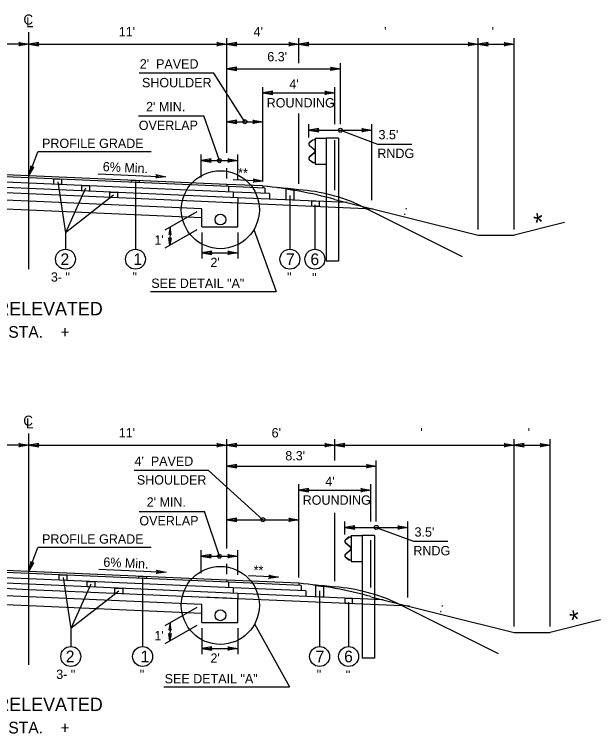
# Model space of a CAD drawing. Extents: x -592 to 1199, y -590 to 416.
# Drawn here: x 814.3 to 902, y 160.9 to 268.6 of the extents above; entities that cross this region are included whole.
import ezdxf

# ---------------------------------------------------------------- set-up
doc = ezdxf.new("R2010")
doc.units = 0
doc.layers.add('1', color=7, linetype='Continuous')
doc.layers.add('Des_ Drain_ Ftrs', color=7, linetype='Continuous')

msp = doc.modelspace()

# ---------------------------------------------------------------- linework, layer by layer
at = {"layer": '1'}
for p, q in [((816.45, 230.46), (816.45, 265.91)), ((846.08, 247.85), (846.08, 265.03)), ((856.86, 261.3), (856.86, 265.03)), ((883.68, 236.42), (883.68, 265.03)), ((889.06, 236.42), (889.06, 265.03)), ((816.45, 264.15), (786.81, 264.15)), ((816.45, 264.15), (846.08, 264.15)), ((846.08, 264.15), (856.86, 264.15)), ((856.86, 264.15), (883.68, 264.15)), ((883.68, 264.15), (889.06, 264.15)), ((863.06, 252.14), (863.06, 261.3)), ((844.12, 259.78), (832.98, 259.78)), ((848.78, 252.52), (844.13, 259.78)), ((846.08, 260.42), (863.06, 260.42)), ((851.47, 243.79), (851.47, 257.72)), ((862.25, 252.14), (862.25, 257.72)), ((851.47, 256.84), (862.25, 256.84)), ((832.88, 253.39), (842.65, 253.39)), ((844.98, 246.72), (842.65, 253.39)), ((856.86, 243.23), (856.86, 253.74)), ((846.08, 252.52), (851.47, 252.52)), ((858.36, 250.19), (858.36, 252.14)), ((867.75, 240.78), (867.75, 252.14)), ((858.36, 251.26), (867.75, 251.26)), ((863.06, 251.26), (868.61, 249.19)), ((858.96, 249.79), (858.45, 249.4)), ((858.97, 249.77), (858.46, 249.38)), ((859.28, 249.85), (858.96, 249.79)), ((859.28, 249.82), (858.97, 249.77)), ((859.28, 250.08), (859.28, 246.15)), ((859.28, 250.08), (860.96, 250.08)), ((860.96, 250.08), (860.96, 231.68)), ((862.79, 250.08), (860.96, 250.08)), ((862.25, 242.26), (862.25, 249.76)), ((862.79, 250.08), (862.79, 231.68)), ((858.43, 248.97), (859.16, 248.34)), ((858.45, 248.99), (859.18, 248.36)), ((868.61, 249.19), (873.77, 249.19)), ((816.45, 244.44), (817.83, 248.01)), ((834.74, 248.01), (817.83, 248.01)), ((842.24, 244.19), (842.24, 247.6)), ((847.73, 243.95), (847.73, 247.6)), ((859.16, 247.89), (858.43, 247.25)), ((859.18, 247.86), (858.45, 247.23)), ((859.25, 248.15), (859.25, 248.07)), ((859.28, 248.15), (859.28, 248.07)), ((842.24, 246.72), (847.73, 246.72)), ((858.45, 246.82), (858.96, 246.43)), ((858.46, 246.84), (858.97, 246.46)), ((816.45, 244.14), (786.47, 245.45)), ((816.45, 244.44), (786.81, 245.73)), ((846.08, 244.02), (846.08, 245.59)), ((858.96, 246.43), (859.28, 246.37)), ((858.97, 246.46), (859.28, 246.4)), ((859.28, 246.15), (860.96, 246.15)), ((816.45, 243.33), (785.55, 244.68)), ((846.09, 243.14), (816.45, 244.44)), ((826.84, 244.74), (836.95, 244.29)), ((816.45, 242.52), (784.62, 243.91)), ((846.32, 242.83), (816.45, 244.14)), ((847.03, 241.99), (816.45, 243.33)), ((820.78, 243.54), (821.94, 235.92)), ((832.41, 243.58), (832.41, 233.43)), ((851.53, 243.65), (847.04, 243.85)), ((816.45, 241.71), (784.64, 243.1)), ((847.73, 241.15), (816.45, 242.52)), ((824.95, 242.56), (821.94, 235.92)), ((851.47, 242.91), (846.09, 243.14)), ((846.09, 243.14), (846.09, 242.84)), ((851.77, 242.6), (846.32, 242.83)), ((846.32, 242.83), (846.32, 242.02)), ((851.47, 242.91), (851.47, 242.61)), ((851.77, 242.6), (851.77, 241.79)), ((816.45, 240.63), (790.01, 241.79)), ((842.25, 240.58), (816.45, 241.71)), ((829.13, 241.55), (821.94, 235.92)), ((852.46, 241.76), (847.03, 241.99)), ((847.03, 241.99), (847.03, 241.18)), ((847.73, 241.15), (847.73, 240.35)), ((864.08, 240.44), (847.73, 241.15)), ((852.46, 241.76), (852.46, 240.95)), ((855.51, 241.48), (855.51, 233.43)), ((858.36, 242.13), (858.36, 242.13)), ((816.45, 239.28), (790.01, 240.44)), ((842.34, 239.5), (816.45, 240.63)), ((847.73, 240.34), (842.25, 240.58)), ((847.74, 240.34), (846.09, 240.42)), ((867.99, 239.46), (847.73, 240.35)), ((847.73, 236.81), (847.73, 240.34)), ((859.25, 240.09), (859.25, 233.43)), ((862.25, 240.9), (883.68, 235.54)), ((842.34, 238.15), (816.45, 239.28)), ((841.58, 239.06), (836.82, 236.31)), ((842.34, 236.81), (842.34, 239.5)), ((842.34, 239.5), (842.34, 239.5)), ((866.25, 239.9), (881.3, 232.37)), ((896.6, 237.42), (889.06, 235.54)), ((821.94, 235.92), (821.94, 233.43)), ((841.58, 236.37), (836.81, 233.61)), ((837.59, 236.75), (837.57, 234.05)), ((842.34, 236.81), (847.73, 236.81)), ((842.34, 235.93), (842.34, 232.04)), ((847.73, 235.93), (847.73, 232.04)), ((850.14, 236.41), (853.47, 227.14)), ((883.68, 235.54), (889.06, 235.54)), ((842.34, 232.92), (847.73, 232.92)), ((862.79, 231.68), (860.96, 231.68)), ((834.68, 227.14), (853.47, 227.14)), ((816.45, 171.24), (816.45, 205.88)), ((846.08, 188.63), (846.08, 205)), ((862.25, 201.84), (862.25, 205)), ((889.07, 176.96), (889.07, 205)), ((894.46, 176.96), (894.46, 205)), ((816.45, 204.12), (786.81, 204.12)), ((816.45, 204.12), (846.08, 204.12)), ((846.08, 204.12), (862.25, 204.12)), ((862.25, 204.12), (889.07, 204.12)), ((889.07, 204.12), (894.46, 204.12)), ((868.44, 192.69), (868.44, 201.84)), ((843.36, 200.32), (832.21, 200.32)), ((851.47, 192.96), (843.36, 200.32)), ((846.08, 200.96), (868.44, 200.96)), ((856.86, 184.33), (856.86, 198.27)), ((867.64, 192.69), (867.64, 198.27)), ((856.86, 197.39), (867.64, 197.39)), ((832.97, 194.21), (842.73, 194.21)), ((844.98, 187.5), (842.73, 194.21)), ((862.25, 183.78), (862.25, 193.99)), ((846.08, 192.96), (856.86, 192.96)), ((863.75, 190.73), (863.75, 192.69)), ((873.14, 181.34), (873.14, 192.69)), ((863.75, 191.81), (873.14, 191.81)), ((868.44, 191.81), (874, 189.73)), ((864.67, 190.62), (864.67, 186.69)), ((864.67, 190.62), (866.35, 190.62)), ((866.35, 190.62), (866.35, 172.22)), ((868.18, 190.62), (866.35, 190.62)), ((868.18, 190.62), (868.18, 172.22)), ((863.82, 189.52), (864.55, 188.88)), ((864.35, 190.34), (863.83, 189.95)), ((863.84, 189.54), (864.57, 188.9)), ((864.36, 190.31), (863.85, 189.92)), ((864.67, 190.39), (864.35, 190.34)), ((864.67, 190.36), (864.36, 190.31)), ((867.64, 182.81), (867.64, 189.88)), ((874, 189.73), (879.16, 189.73)), ((816.45, 185.22), (817.83, 188.79)), ((834.74, 188.79), (817.83, 188.79)), ((842.24, 184.97), (842.24, 188.38)), ((847.73, 184.73), (847.73, 188.38)), ((864.55, 188.43), (863.82, 187.79)), ((864.57, 188.41), (863.84, 187.77)), ((864.64, 188.69), (864.64, 188.62)), ((864.67, 188.69), (864.67, 188.62)), ((842.24, 187.5), (847.73, 187.5)), ((863.83, 187.36), (864.35, 186.97)), ((863.85, 187.39), (864.36, 187)), ((816.45, 184.92), (786.47, 186.23)), ((816.45, 185.22), (786.81, 186.51)), ((846.08, 184.8), (846.08, 186.37)), ((864.35, 186.97), (864.67, 186.92)), ((864.36, 187), (864.67, 186.95)), ((864.67, 186.69), (866.35, 186.69)), ((816.45, 184.11), (785.55, 185.46)), ((846.09, 183.92), (816.45, 185.22)), ((826.91, 185.54), (837.02, 185.1)), ((816.45, 183.3), (784.62, 184.69)), ((846.32, 183.61), (816.45, 184.92)), ((847.03, 182.77), (816.45, 184.11)), ((821.58, 184.29), (822.74, 176.66)), ((833.48, 184.3), (833.48, 173.98)), ((853.83, 184.34), (849.34, 184.54)), ((816.45, 182.49), (784.62, 183.88)), ((847.73, 181.93), (816.45, 183.3)), ((825.75, 183.3), (822.74, 176.66)), ((856.86, 183.45), (846.09, 183.92)), ((846.09, 183.92), (846.09, 183.62)), ((846.32, 183.61), (846.32, 182.8)), ((857.19, 183.14), (846.33, 183.61)), ((856.86, 183.45), (856.86, 183.15)), ((857.19, 183.14), (857.19, 182.33)), ((816.45, 181.41), (790.01, 182.57)), ((847.73, 181.12), (816.45, 182.49)), ((829.93, 182.29), (822.74, 176.66)), ((847.03, 182.77), (847.03, 181.96)), ((857.89, 182.3), (847.04, 182.77)), ((847.73, 181.93), (847.73, 181.12)), ((869.48, 180.98), (847.75, 181.93)), ((857.89, 182.3), (857.89, 181.49)), ((859.96, 182.32), (859.96, 173.98)), ((863.75, 182.67), (863.75, 182.67)), ((816.45, 180.06), (790.01, 181.22)), ((842.34, 180.28), (816.45, 181.41)), ((846.08, 181.2), (842.25, 181.36)), ((847.73, 181.12), (846.07, 181.2)), ((847.73, 177.59), (847.73, 181.12)), ((873.39, 180), (847.73, 181.12)), ((867.64, 181.44), (889.07, 176.08)), ((842.34, 178.93), (816.45, 180.06)), ((841.58, 179.84), (836.82, 177.09)), ((842.34, 177.59), (842.34, 180.28)), ((842.34, 180.28), (842.34, 180.28)), ((864.3, 180.63), (864.3, 173.98)), ((871.64, 180.44), (886.69, 172.92)), ((902, 177.97), (894.46, 176.08)), ((822.74, 176.66), (822.74, 173.98)), ((841.58, 177.15), (836.81, 174.39)), ((837.59, 177.53), (837.57, 174.83)), ((842.34, 177.59), (847.73, 177.59)), ((842.34, 176.71), (842.34, 172.82)), ((847.73, 176.71), (847.73, 172.82)), ((850.24, 177.36), (855.46, 167.97)), ((889.07, 176.08), (894.46, 176.08)), ((842.34, 173.7), (847.73, 173.7)), ((868.18, 172.22), (866.35, 172.22)), ((836.68, 167.97), (855.46, 167.97))]:
    msp.add_line(p, q, dxfattribs=at)
for points in [[(820.21, 243.97), (821.35, 243.92), (821.35, 243.11), (820.21, 243.16)], [(831.83, 243.77), (832.98, 243.71), (832.98, 243.42), (831.83, 243.47)], [(824.38, 242.98), (825.53, 242.93), (825.53, 242.12), (824.38, 242.17)], [(854.94, 242.46), (856.08, 242.27), (856.08, 240.79), (854.94, 240.84)], [(828.56, 241.99), (829.7, 241.94), (829.7, 241.13), (828.56, 241.18)], [(858.79, 240.68), (859.9, 240.63), (859.9, 239.82), (858.79, 239.87)], [(821, 184.72), (822.15, 184.67), (822.15, 183.86), (821, 183.91)], [(832.91, 184.5), (834.06, 184.45), (834.06, 184.15), (832.91, 184.2)], [(825.18, 183.73), (826.32, 183.68), (826.32, 182.87), (825.18, 182.92)], [(859.39, 183.14), (860.53, 182.97), (860.53, 181.37), (859.39, 181.42)], [(829.35, 182.73), (830.5, 182.68), (830.5, 181.88), (829.35, 181.93)], [(863.76, 181.23), (864.81, 181.19), (864.81, 180.38), (863.76, 180.43)]]:
    msp.add_lwpolyline(points, close=True, dxfattribs=at)
for centre, radius in [((848.78, 252.52), 0.3), ((863.06, 251.26), 0.3), ((844.98, 246.72), 0.3), ((845.11, 239.36), 5.84), ((845.12, 237.88), 0.808), ((821.94, 231.95), 1.49), ((832.41, 231.95), 1.49), ((855.51, 231.95), 1.49), ((859.25, 231.95), 1.49), ((851.47, 192.96), 0.3), ((868.44, 191.81), 0.3), ((844.98, 187.5), 0.3), ((845.11, 180.14), 5.84), ((845.12, 178.66), 0.808), ((822.74, 172.49), 1.49), ((833.48, 172.49), 1.49), ((859.96, 172.49), 1.49), ((864.3, 172.49), 1.49)]:
    msp.add_circle(centre, radius, dxfattribs=at)
for centre, radius, start, end in [((858.61, 249.18), 0.278, 126.9799, 229.021), ((858.61, 249.18), 0.249, 126.9799, 229.021), ((859, 248.15), 0.249, 0, 49.0365), ((859, 248.07), 0.249, 310.9635, 0), ((859, 248.15), 0.278, 0, 49.0365), ((859, 248.07), 0.278, 310.9635, 0), ((858.61, 247.04), 0.278, 130.979, 233.0201), ((858.61, 247.04), 0.249, 130.979, 233.0201), ((844.59, 176.07), 67.19, 74.7593, 84.1179), ((846.04, 141.69), 101.24, 83.8633, 85.6775), ((854.74, 215.07), 27.37, 65.1374, 85.5513), ((864, 189.73), 0.278, 126.9799, 229.021), ((864, 189.73), 0.249, 126.9799, 229.021), ((864.39, 188.69), 0.249, 0, 49.0365), ((864.39, 188.62), 0.249, 310.9635, 0), ((864.39, 188.69), 0.278, 0, 49.0365), ((864.39, 188.62), 0.278, 310.9635, 0), ((864, 187.58), 0.278, 130.979, 233.0201), ((864, 187.58), 0.249, 130.979, 233.0201), ((849.98, 116.62), 67.19, 74.7602, 84.1188), ((851.43, 82.23), 101.24, 83.8633, 85.6775), ((860.13, 155.61), 27.37, 65.1374, 85.5513)]:
    msp.add_arc(centre, radius, start, end, dxfattribs=at)
at = {"layer": 'Des_ Drain_ Ftrs'}
for points in [[(816.45, 264.15), (814.96, 263.9), (815.26, 264.15), (814.96, 264.4)], [(816.45, 264.15), (817.94, 263.9), (817.64, 264.15), (817.94, 264.4)], [(846.08, 264.15), (844.6, 263.9), (844.89, 264.15), (844.6, 264.4)], [(846.08, 264.15), (847.57, 263.9), (847.28, 264.15), (847.57, 264.4)], [(856.86, 264.15), (855.37, 263.9), (855.67, 264.15), (855.37, 264.4)], [(856.86, 264.15), (858.35, 263.9), (858.05, 264.15), (858.35, 264.4)], [(883.68, 264.15), (882.19, 263.9), (882.48, 264.15), (882.19, 264.4)], [(883.68, 264.15), (885.16, 263.9), (884.87, 264.15), (885.16, 264.4)], [(889.06, 264.15), (887.58, 263.9), (887.87, 264.15), (887.58, 264.4)], [(846.08, 260.42), (847.57, 260.17), (847.28, 260.42), (847.57, 260.67)], [(863.06, 260.42), (861.57, 260.17), (861.86, 260.42), (861.57, 260.67)], [(851.47, 256.84), (852.96, 256.6), (852.67, 256.84), (852.96, 257.09)], [(862.25, 256.84), (860.76, 256.6), (861.06, 256.84), (860.76, 257.09)], [(846.08, 252.52), (847.57, 252.27), (847.28, 252.52), (847.57, 252.77)], [(851.47, 252.52), (849.98, 252.27), (850.28, 252.52), (849.98, 252.77)], [(858.36, 251.26), (859.85, 251.01), (859.56, 251.26), (859.85, 251.51)], [(867.75, 251.26), (866.26, 251.01), (866.56, 251.26), (866.26, 251.51)], [(842.24, 246.72), (843.73, 246.47), (843.43, 246.72), (843.73, 246.97)], [(847.73, 246.72), (846.24, 246.47), (846.53, 246.72), (846.24, 246.97)], [(816.45, 244.44), (817.21, 245.74), (816.88, 245.55), (816.75, 245.92)], [(836.95, 244.29), (835.45, 244.11), (835.76, 244.35), (835.47, 244.61)], [(851.53, 243.65), (850.03, 243.47), (850.34, 243.7), (850.05, 243.96)], [(837.59, 236.75), (837.4, 235.67), (837.58, 235.88), (837.76, 235.67)], [(837.57, 234.05), (837.39, 235.13), (837.57, 234.92), (837.75, 235.13)], [(842.34, 232.92), (843.83, 232.67), (843.54, 232.92), (843.83, 233.17)], [(847.73, 232.92), (846.24, 232.67), (846.54, 232.92), (846.24, 233.17)], [(816.45, 204.12), (814.96, 203.87), (815.26, 204.12), (814.96, 204.37)], [(816.45, 204.12), (817.94, 203.87), (817.64, 204.12), (817.94, 204.37)], [(846.08, 204.12), (844.6, 203.87), (844.89, 204.12), (844.6, 204.37)], [(846.08, 204.12), (847.57, 203.87), (847.28, 204.12), (847.57, 204.37)], [(862.25, 204.12), (860.76, 203.87), (861.06, 204.12), (860.76, 204.37)], [(862.25, 204.12), (863.74, 203.87), (863.44, 204.12), (863.74, 204.37)], [(889.07, 204.12), (887.58, 203.87), (887.88, 204.12), (887.58, 204.37)], [(889.07, 204.12), (890.56, 203.87), (890.27, 204.12), (890.56, 204.37)], [(894.46, 204.12), (892.97, 203.87), (893.27, 204.12), (892.97, 204.37)], [(846.08, 200.96), (847.57, 200.71), (847.28, 200.96), (847.57, 201.21)], [(868.44, 200.96), (866.96, 200.71), (867.25, 200.96), (866.96, 201.21)], [(856.86, 197.39), (858.35, 197.14), (858.05, 197.39), (858.35, 197.64)], [(867.64, 197.39), (866.15, 197.14), (866.44, 197.39), (866.15, 197.64)], [(846.08, 192.96), (847.57, 192.71), (847.28, 192.96), (847.57, 193.21)], [(856.86, 192.96), (855.37, 192.71), (855.67, 192.96), (855.37, 193.21)], [(863.75, 191.81), (865.24, 191.56), (864.95, 191.81), (865.24, 192.05)], [(873.14, 191.81), (871.65, 191.56), (871.94, 191.81), (871.65, 192.05)], [(842.24, 187.5), (843.73, 187.25), (843.43, 187.5), (843.73, 187.75)], [(847.73, 187.5), (846.24, 187.25), (846.53, 187.5), (846.24, 187.75)], [(816.45, 185.22), (817.21, 186.52), (816.88, 186.33), (816.75, 186.7)], [(837.02, 185.1), (835.53, 184.91), (835.83, 185.15), (835.55, 185.41)], [(853.83, 184.34), (852.33, 184.16), (852.64, 184.39), (852.35, 184.65)], [(837.59, 177.53), (837.4, 176.45), (837.58, 176.66), (837.76, 176.45)], [(837.57, 174.83), (837.39, 175.91), (837.57, 175.7), (837.75, 175.91)], [(842.34, 173.7), (843.83, 173.45), (843.54, 173.7), (843.83, 173.95)], [(847.73, 173.7), (846.24, 173.45), (846.54, 173.7), (846.24, 173.95)]]:
    msp.add_lwpolyline(points, close=True, dxfattribs=at)

# ---------------------------------------------------------------- texts
at = {"layer": '1'}
for s, height, p in [("11'", 1.4, (829.92, 265.3)), ("4'", 1.4, (850.08, 265.3)), ("  '", 1.4, (868.57, 265.3)), (" '", 1.4, (885.18, 265.3)), ("6.3'", 1.4, (852.13, 261.57)), ("2'  PAVED", 1.4, (833.06, 260.48)), ('SHOULDER', 1.4, (833.39, 257.68)), ("4'", 1.4, (855.43, 257.46)), ("2' MIN.", 1.4, (834, 254.09)), ('ROUNDING', 1.4, (852.04, 254.66)), ('OVERLAP', 1.4, (832.91, 251.29)), ("3.5'", 1.4, (868.77, 249.89)), ('PROFILE GRADE', 1.4, (818.44, 248.59)), ('RNDG', 1.4, (868.6, 247.09)), ('2', 1.75, (821.2, 231.07)), ('1', 1.75, (832.1, 231.07)), ('7', 1.75, (854.92, 231.07)), ('6', 1.75, (858.59, 231.07)), ("2'", 1.4, (843.63, 230.77)), ('3- "', 1.4, (819.76, 228.59)), (' "', 1.4, (831.46, 228.59)), (' "', 1.4, (854.57, 228.59)), (' "', 1.4, (858.31, 228.49)), ('SEE DETAIL "A"', 1.4, (834.78, 227.65)), ('SUPERELEVATED', 2, (804.33, 223.55)), ('STA.    +      TO STA.    +     ', 1.75, (796.42, 220.19)), ("6'", 1.4, (852.78, 205.27)), ("11'", 1.4, (829.92, 205.27)), ("  '", 1.4, (873.97, 205.27)), (" '", 1.4, (890.57, 205.27)), ("4'  PAVED", 1.4, (832.27, 201.02)), ("8.3'", 1.4, (854.83, 201.84)), ('SHOULDER', 1.4, (832.62, 198.22)), ("4'", 1.4, (860.82, 198)), ("2' MIN.", 1.4, (834.09, 194.91)), ('ROUNDING', 1.4, (857.43, 195.2)), ('OVERLAP', 1.4, (833, 192.11)), ("3.5'", 1.4, (874.16, 190.43)), ('PROFILE GRADE', 1.4, (818.44, 189.37)), ('RNDG', 1.4, (873.99, 187.63)), ('2', 1.75, (821.99, 171.62)), ('1', 1.75, (833.18, 171.62)), ('7', 1.75, (859.37, 171.62)), ('6', 1.75, (863.63, 171.62)), ("2'", 1.4, (843.63, 171.55)), ('3- "', 1.4, (820.56, 169.13)), (' "', 1.4, (832.54, 169.13)), (' "', 1.4, (859.01, 169.13)), (' "', 1.4, (863.35, 169.04)), ('SEE DETAIL "A"', 1.4, (836.78, 168.47)), ('SUPERELEVATED', 2, (804.33, 164.33)), ('STA.    +      TO STA.    +     ', 1.75, (796.42, 160.97))]:
    msp.add_text(s, height=height, dxfattribs=at).set_placement(p)
for s, height, rotation, p in [('6% Min.', 1.4, 357.3731, (827.5, 245.13)), ('**', 1.4, 357.2169, (847.72, 244.21)), (' : ', 1.4, 345.7718, (871.91, 238.77)), ('*', 2.8, 12.8479, (892.38, 235.94)), ("1'", 1.4, 0.1438, (835.24, 234.14)), ('6% Min.', 1.4, 357.3727, (827.58, 185.94)), ('**', 1.4, 357.2168, (850.05, 184.75)), (' : ', 1.4, 345.7718, (877.31, 179.31)), ('*', 2.8, 12.8479, (897.78, 176.49)), ("1'", 1.4, 0.1438, (835.24, 174.92))]:
    msp.add_text(s, height=height, rotation=rotation, dxfattribs=at).set_placement(p)
at = {"layer": 'Des_ Drain_ Ftrs'}
for s, p in [('C', (815.65, 267.07)), ('L', (816.05, 266.67)), ('C', (815.63, 207.04)), ('L', (816.02, 206.64))]:
    msp.add_text(s, height=1.5, dxfattribs=at).set_placement(p)

doc.saveas('drawing.dxf')
